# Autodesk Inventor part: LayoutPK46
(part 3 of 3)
    geometry: L1 (36.508, 713.207)-(-16.797, 670.2); L2 (-16.797, 670.2)-(-101.739, 335.484); L3 (-101.739, 335.484)-(-109.966, 2.719); L4 (8.288, -109.687)-(308.835, -86.978); L5 (308.835, -86.978)-(319.542, -83.051); L6 (19.324, 520.756)-(99.155, 741.781); L7 (99.155, 741.781)-(80.344, 748.575); L8 (80.344, 748.575)-(36.508, 713.207); L9 (1233.625, 258.517)-(1200.234, 261.682); L10 (1200.234, 261.682)-(1143.868, 239.874); L11 (1143.868, 239.874)-(1177.667, 236.867); L12 (1177.667, 236.867)-(1233.625, 258.517); L13 (967.076, 171.475)-(1143.868, 239.874); L14 (1181.276, 227.541)-(976.097, 148.159); L15 (976.097, 148.159)-(967.076, 171.475); L16 (1237.234, 249.191)-(1233.625, 258.517); L17 (1177.667, 236.867)-(1181.276, 227.541); L18 (1181.276, 227.541)-(1237.234, 249.191); L19 (332.219, -99.88)-(327.869, -88.635); L20 (332.219, -99.88)-(340.093, -96.834); L21 (327.869, -88.635)-(326.446, -84.958); L22 (630.662, 15.585)-(695.946, 40.843); L23 (340.093, -96.834)-(630.662, 15.585); L24 (971.406, 160.283)-(964.544, 144.762); L25 (971.406, 160.283)-(969.963, 164.014); L26 (695.946, 40.843)-(690.173, 55.765); L27 (969.963, 164.014)-(690.173, 55.765); L28 (695.946, 40.843)-(964.544, 144.762); L29 (271.723, 1081.905)-(246.908, 1104.472); L30 (246.908, 1104.472)-(15.69, 814.708); L31 (11.012, 759.335)-(43.462, 700.624); L32 (47.21, 660.849)-(-0.759, 514.651); L33 (556.412, -14.214)-(696.307, 39.911); L34 (696.307, 39.911)-(695.946, 40.843); L35 (594.585, 649.257)-(271.723, 1081.905); L36 (459.694, 596.673)-(459.353, 596.937); L37 (459.353, 596.937)-(498.23, 611.978); L38 (1112.062, 227.901)-(576.694, 642.28); L39 (995.062, 182.294)-(998.041, 183.455); L40 (499.228, 612.083)-(459.694, 596.673); L41 (459.694, 596.673)-(526.939, 544.624); L42 (606.946, 482.699)-(686.952, 420.773); L43 (766.958, 358.848)-(846.965, 296.922); L44 (926.971, 234.997)-(985.819, 189.448); L45 (995.055, 182.3)-(995.062, 182.294); L46 (998.041, 183.455)-(1130.882, 235.237); L47 (985.819, 189.448)-(995.055, 182.3); L48 (1130.882, 235.237)-(595.514, 649.616); C1 r 60 at (0, 0); C2 r 85 at (-189.66, 366.918); C3 r 25 at (54.772, 783.522); C4 r 62.5 at (-189.66, 366.918); A1 r 110 centre (0, 0) between (-109.966, 2.719) and (8.288, -109.687); A2 r 408 centre (403.06, 382.155) between (19.324, 520.756) and (16.94, 513.969); A3 r 50 centre (54.772, 783.522) between (15.69, 814.708) and (11.012, 759.335); A4 r 50 centre (-0.298, 676.437) between (47.21, 660.849) and (43.462, 700.624); A5 r 425 centre (403.06, 382.155) between (-0.759, 514.651) and (556.412, -14.214); 1 further point
    constraints: 96 end point, 10 point on circle, 9 centre point, 6 point on line
  sketch "A$C70327705_4"
    geometry: L1 (1293.342, 14.877)-(652.519, 14.877); L2 (1112.519, 47.877)-(1112.519, 51.877); L3 (652.519, 25)-(652.519, 14.997); L4 (652.519, 0)-(437.177, 0); L5 (437.177, 0)-(416.627, 29.348); L6 (662.519, 24.877)-(652.519, 24.877); L7 (1392.519, 34.877)-(1392.519, 44.877); L8 (1112.519, 34.877)-(1112.519, 59.877); L9 (1293.342, 34.877)-(1112.519, 34.877); L10 (1112.519, 59.877)-(1362.519, 59.877); L11 (1392.519, 44.877)-(1362.519, 59.877); L12 (936.663, 615.946)-(1277.997, 59.877); L13 (432.979, 926.11)-(441.861, 861.091); L14 (777.519, 1162.877)-(457.322, 976.064); L15 (116.871, 116.614)-(247.396, 77.132); L16 (100.413, 392.297)-(47.142, 264.117); L17 (374.881, 853.013)-(360.531, 832.814); L18 (440.113, 873.889)-(374.881, 853.013); L19 (9.07, 588.157)-(247.396, 77.132); L20 (662.519, 24.877)-(1293.342, 24.877); L21 (662.519, 34.877)-(1293.342, 34.877); L22 (679.974, 1088.415)-(349.973, 695.135); L23 (686.501, 1080.636)-(357.633, 688.707); L24 (1293.342, 14.877)-(1293.342, 24.877); L25 (1293.342, 24.877)-(1293.342, 34.877); L26 (936.663, 615.946)-(784.916, 1137.456); L27 (782.039, 1147.342)-(777.519, 1162.877); L28 (874.123, 1234.796)-(868.202, 1201.213); L29 (883.971, 1233.059)-(878.05, 1199.476); L30 (863.354, 1194.289)-(679.974, 1088.415); L31 (874.123, 1234.796)-(883.971, 1233.059); L32 (1293.342, 34.877)-(1392.519, 34.877); L33 (686.501, 1080.636)-(868.354, 1185.629); L34 (652.519, 0)-(652.519, 14.997); L35 (602.285, 29.348)-(293.569, 29.348); L36 (259.584, 50.998)-(247.396, 77.132); L37 (69.748, 731.714)-(508.737, 884.343); C1 r 25 at (482.519, 932.877); C2 r 45 at (104.231, 632.537); A1 r 50 centre (482.519, 932.877) between (457.322, 976.064) and (432.979, 926.11); A2 r 40 centre (148.72, 221.902) between (162.34, 259.512) and (186.286, 208.165); A3 r 110 centre (148.72, 221.902) between (47.142, 264.117) and (116.871, 116.614); A4 r 105 centre (104.231, 632.537) between (69.748, 731.714) and (9.07, 588.157); A5 r 408 centre (662.519, 432.877) between (349.973, 695.135) and (662.519, 24.877); A6 r 398 centre (662.519, 432.877) between (357.633, 688.707) and (662.519, 34.877); A7 r 37.5 centre (293.569, 66.848) between (259.584, 50.998) and (293.569, 29.348); A8 r 10 centre (858.354, 1202.949) between (863.354, 1194.289) and (868.202, 1201.213); A9 r 20 centre (858.354, 1202.949) between (868.354, 1185.629) and (878.05, 1199.476); 1 further point
    constraints: 74 end point, 20 point on circle, 16 point on line, 11 centre point
  sketch "A$C60B60B97_4"
    geometry: 1 further point
  sketch "Borders Default Border_9.00X_5"
    geometry: L1 (171.45, 114.3)-(171.45, 3771.9); L2 (171.45, 3771.9)-(4857.75, 3771.9); L3 (4857.75, 3771.9)-(4857.75, 114.3); L4 (4857.75, 114.3)-(171.45, 114.3); L5 (2514.6, 57.15)-(2514.6, 114.3); L6 (2514.6, 114.3)-(2494.803, 80.01); L7 (2494.803, 80.01)-(2534.397, 80.01); L8 (2534.397, 80.01)-(2514.6, 114.3); L9 (2514.6, 3829.05)-(2514.6, 3771.9); L10 (2514.6, 3771.9)-(2494.803, 3806.19); L11 (2494.803, 3806.19)-(2534.397, 3806.19); L12 (2534.397, 3806.19)-(2514.6, 3771.9); L13 (114.3, 1943.1)-(171.45, 1943.1); L14 (171.45, 1943.1)-(137.16, 1962.897); L15 (137.16, 1962.897)-(137.16, 1923.303); L16 (137.16, 1923.303)-(171.45, 1943.1); L17 (4914.9, 1943.1)-(4857.75, 1943.1); L18 (4857.75, 1943.1)-(4892.04, 1962.897); L19 (4892.04, 1962.897)-(4892.04, 1923.303); L20 (4892.04, 1923.303)-(4857.75, 1943.1); L21 (1257.3, 114.3)-(1257.3, 77.724); L22 (1257.3, 3771.9)-(1257.3, 3808.476); L23 (3771.9, 114.3)-(3771.9, 77.724); L24 (3771.9, 3771.9)-(3771.9, 3808.476); L25 (171.45, 971.55)-(134.874, 971.55); L26 (4857.75, 971.55)-(4894.326, 971.55); L27 (171.45, 2914.65)-(134.874, 2914.65); L28 (4857.75, 2914.65)-(4894.326, 2914.65); 17 further points
    constraints: 56 end point, 8 point on line, 4 midpoint, 16 other
  sketch "_Closed_6"
    geometry: L1 (-25.4, 4.233)-(0, 0); L2 (0, 0)-(-25.4, -4.233); L3 (-25.4, 4.233)-(-25.4, -4.233); L4 (0, 0)-(-25.4, 0); 1 further point
    constraints: 8 end point, 1 midpoint
  sketch "DatumFilled45_6"
    geometry: L1 (0, 25.4)-(0, -25.4); L2 (0, -25.4)-(-25.4, 0); L3 (-25.4, 0)-(0, 25.4); L4 (0, 25.4)-(0, -25.4); L5 (0, -25.4)-(0, 25.4); L6 (0, 25.4)-(-25.4, 0); L7 (-25.4, 0)-(0, 25.4); 1 further point
    constraints: 14 end point
  sketch "Filled-1_6"
    geometry: L1 (-25.4, 0)-(0, 0); L2 (-25.4, -2.527)-(0, 0); L3 (0, 0)-(-25.4, 2.527); L4 (-25.4, 2.527)-(-25.4, -2.527); L5 (-25.4, -2.527)-(0, 0); L6 (0, 0)-(-25.4, -2.527); L7 (-25.4, -2.527)-(-25.4, 2.527); L8 (-25.4, 2.527)-(-25.4, -2.527); L9 (-25.4, -2.527)-(0, 0); L10 (0, 0)-(-25.4, 2.527); L11 (-25.4, 2.527)-(-25.4, -2.527); 1 further point
    constraints: 22 end point, 4 midpoint
  sketch "Borders Default Border_6"
    geometry: L1 (19.05, 12.7)-(19.05, 419.1); L2 (19.05, 419.1)-(539.75, 419.1); L3 (539.75, 419.1)-(539.75, 12.7); L4 (539.75, 12.7)-(19.05, 12.7); L5 (279.4, 6.35)-(279.4, 12.7); L6 (279.4, 12.7)-(277.2, 8.89); L7 (277.2, 8.89)-(281.6, 8.89); L8 (281.6, 8.89)-(279.4, 12.7); L9 (279.4, 425.45)-(279.4, 419.1); L10 (279.4, 419.1)-(277.2, 422.91); L11 (277.2, 422.91)-(281.6, 422.91); L12 (281.6, 422.91)-(279.4, 419.1); L13 (12.7, 215.9)-(19.05, 215.9); L14 (19.05, 215.9)-(15.24, 218.1); L15 (15.24, 218.1)-(15.24, 213.7); L16 (15.24, 213.7)-(19.05, 215.9); L17 (546.1, 215.9)-(539.75, 215.9); L18 (539.75, 215.9)-(543.56, 218.1); L19 (543.56, 218.1)-(543.56, 213.7); L20 (543.56, 213.7)-(539.75, 215.9); L21 (139.7, 12.7)-(139.7, 8.636); L22 (139.7, 419.1)-(139.7, 423.164); L23 (419.1, 12.7)-(419.1, 8.636); L24 (419.1, 419.1)-(419.1, 423.164); L25 (19.05, 107.95)-(14.986, 107.95); L26 (539.75, 107.95)-(543.814, 107.95); L27 (19.05, 323.85)-(14.986, 323.85); L28 (539.75, 323.85)-(543.814, 323.85); 17 further points
    constraints: 56 end point, 8 point on line, 4 midpoint, 16 other
  sketch "GENAXEH_6"
    geometry: L1 (-25.4, 0)-(25.4, 0); 1 further point
    constraints: 2 end point
  sketch "Weldment_6"
    geometry: L1 (-362.49, 605.558)-(-187.308, 59.988); L2 (-48.402, -559.479)-(-89.17, -792.346); L3 (104.596, -840)-(155.018, -682.036); L4 (176.996, -25.915)-(5.037, 246.17); L5 (5.037, 246.17)-(-175.085, 674.867); L6 (-187.308, 59.988)-(-152.339, -48.916); L7 (-104.241, -121.383)-(-75.352, -146.192); L8 (-8.649, -332.41)-(-48.402, -559.479); L9 (155.018, -682.036)-(230.654, -445.083); L10 (-57.997, -88.254)-(-54.949, -85.206); L11 (-57.997, -85.206)-(-54.949, -88.254); C1 r 75 at (0, 0); C2 r 87 at (0, 0); C3 r 45 at (-267.278, 636.131); C4 r 45 at (9.332, -809.591); C5 r 1.524 at (-56.473, -86.73); A1 r 100 centre (-267.278, 636.131) between (-175.085, 674.867) and (-362.49, 605.558); A2 r 100 centre (9.332, -809.591) between (-89.17, -792.346) and (104.596, -840); A3 r 500 centre (-245.668, -293.04) between (250.28, -356.567) and (176.996, -25.915); A4 r 160 centre (0, 0) between (-152.339, -48.916) and (-104.241, -121.383); A5 r 200 centre (-205.653, -297.921) between (-8.649, -332.41) and (-75.352, -146.192); A6 r 500 centre (-245.668, -293.04) between (230.654, -445.083) and (250.28, -356.567); 1 further point
    constraints: 22 end point, 12 point on circle, 11 centre point
  sketch "Connector_6"
    geometry: L1 (157.164, 27.531)-(232.989, 74.957); L2 (483.604, 231.708)-(512.662, 249.882); L3 (76.449, -64.463)-(145.454, 17.372); L4 (449.028, 351.621)-(398.755, 320.177); L5 (509.104, 419.139)-(460.738, 361.78); L6 (526.921, 255.966)-(571.21, 267.162); L7 (232.989, 74.957)-(483.604, 231.708); L8 (398.755, 320.177)-(93.53, 129.27); L9 (529.743, 443.615)-(509.104, 419.139); L10 (79.271, 123.186)-(-24.509, 96.95); L11 (571.21, 267.162)-(630.701, 282.202); L12 (302.321, 205.82)-(305.369, 208.868); L13 (302.321, 208.868)-(305.369, 205.82); C1 r 45 at (0, 0); C2 r 45 at (606.192, 379.152); C3 r 1.524 at (303.845, 207.344); A1 r 50 centre (539.176, 207.491) between (526.921, 255.966) and (512.662, 249.882); A2 r 50 centre (183.678, -14.86) between (157.164, 27.531) and (145.454, 17.372); A3 r 50 centre (422.514, 394.012) between (449.028, 351.621) and (460.738, 361.78); A4 r 50 centre (67.016, 171.661) between (79.271, 123.186) and (93.53, 129.27); A5 r 100 centre (606.192, 379.152) between (630.701, 282.202) and (529.743, 443.615); A6 r 100 centre (0, 0) between (-24.509, 96.95) and (76.449, -64.463); 1 further point
    constraints: 26 end point, 12 point on circle, 9 centre point
  sketch "Base_6"
    geometry: L1 (278.529, -481.687)-(299.453, -447.453); L2 (295.917, -416.857)-(172.052, -291.319); L3 (95.022, -681.286)-(272.857, -489.184); L4 (108.329, 19.101)-(158.403, -264.884); L5 (-225.117, -660.979)-(-108.413, 18.617); L6 (-225.235, -722.613)-(-225.117, -660.979); L7 (-198.661, -766.881)-(-24.713, -859.13); L8 (3.19, -856.093)-(33.762, -830.109); L9 (48.097, -808.832)-(84.242, -699.551); L10 (0, 254)-(0, -254); L11 (-254, 0)-(254, 0); L12 (0, -346)-(0, -854); L13 (-254, -600)-(254, -600); L14 (37.419, -377.546)-(40.467, -374.498); L15 (37.419, -374.498)-(40.467, -377.546); C1 r 40 at (0, -600); C2 r 40 at (0, 0); C3 r 1.524 at (38.943, -376.022); A1 r 47.5 centre (238, -456.916) between (272.857, -489.184) and (278.529, -481.687); A2 r 25 centre (278.122, -434.416) between (299.453, -447.453) and (295.917, -416.857); A3 r 50 centre (207.644, -256.202) between (158.403, -264.884) and (172.052, -291.319); A4 r 50 centre (-175.235, -722.709) between (-225.235, -722.613) and (-198.661, -766.881); A5 r 50 centre (131.713, -715.252) between (95.022, -681.286) and (84.242, -699.551); A6 r 110 centre (0, 0) between (108.329, 19.101) and (-108.413, 18.617); A7 r 25 centre (-13, -837.043) between (-24.713, -859.13) and (3.19, -856.093); A8 r 47.5 centre (3, -793.916) between (33.762, -830.109) and (48.097, -808.832); 1 further point
    constraints: 30 end point, 16 point on circle, 11 centre point
  sketch "CenterSpan_6"
    geometry: L1 (273.969, -185.044)-(234.974, -284.945); L2 (36.362, 93.155)-(259.933, 5.887); L3 (12.317, -103.462)-(-16.542, -98.622); L4 (180.828, -183.299)-(-38.18, -97.813); L5 (437.598, -26.221)-(296.603, -162.71); L6 (-23.266, 102.39)-(214.339, 156.38); L7 (495.815, 30.136)-(437.598, -26.221); L8 (214.339, 156.38)-(404.104, 199.5); L9 (110.262, -93.996)-(113.31, -90.948); L10 (110.262, -90.948)-(113.31, -93.996); C1 r 82 at (0, 0); C2 r 82 at (223.572, -87.268); C3 r 50 at (426.262, 101.986); C4 r 58.472 at (158.121, -254.947); C5 r 1.524 at (111.786, -92.472); A1 r 90 centre (-2.571, -192.223) between (81.268, -224.948) and (12.317, -103.462); A2 r 60 centre (329.862, -206.861) between (290.003, -162.013) and (273.969, -185.044); A3 r 100 centre (223.572, -87.267) between (290.003, -162.013) and (259.933, 5.887); A4 r 100 centre (0, 0) between (36.362, 93.155) and (-16.542, -98.622); A5 r 105 centre (223.572, -87.268) between (189.942, -186.736) and (296.603, -162.71); A6 r 105 centre (0, 0) between (-23.266, 102.39) and (-38.18, -97.813); A7 r 100 centre (426.262, 101.986) between (495.815, 30.136) and (404.104, 199.5); A8 r 82.5 centre (158.121, -254.946) between (81.268, -224.948) and (234.974, -284.944); 1 further point
    constraints: 20 end point, 17 point on circle, 13 centre point, 1 point on line
  sketch "Arm_6"
    geometry: L1 (-25.496, -107.005)-(137.409, -145.82); L2 (2597.068, -901.099)-(2521.421, -896.025); L3 (2257.231, -771.408)-(2076.35, -579.673); L4 (2076.35, -579.673)-(2063.205, -583.463); L5 (2043.846, -578.704)-(1704.981, -254.849); L6 (1379.251, -95.221)-(16.283, 108.788); L7 (137.409, -145.82)-(1374.243, -440.518); L8 (1601.431, -691.827)-(2199.578, -1052.198); L9 (2469.644, -1123.775)-(2592.355, -1120.82); L10 (1293.329, -509.09)-(1296.377, -506.042); L11 (1293.329, -506.042)-(1296.377, -509.09); C1 r 40.528 at (0, 0); C2 r 40.528 at (2589.706, -1010.852); C3 r 1.524 at (1294.853, -507.566); A1 r 400 centre (2548.19, -496.921) between (2482.623, -891.511) and (2521.421, -896.025); A2 r 110 centre (2589.706, -1010.852) between (2597.994, -1120.539) and (2597.068, -901.099); A3 r 400 centre (2548.19, -496.921) between (2257.231, -771.408) and (2482.623, -891.511); A4 r 20 centre (2057.664, -564.246) between (2043.846, -578.704) and (2063.205, -583.463); A5 r 600 centre (1290.432, -688.61) between (1704.981, -254.849) and (1379.251, -95.221); A6 r 70 centre (1358.018, -508.612) between (1423.227, -534.065) and (1374.243, -440.518); A7 r 100 centre (1516.382, -570.427) between (1423.227, -534.065) and (1519.438, -670.38); A8 r 150 centre (1524.023, -820.31) between (1601.431, -691.827) and (1519.438, -670.38); A9 r 500 centre (2457.606, -623.92) between (2199.578, -1052.198) and (2469.644, -1123.775); A10 r 110 centre (0, 0) between (16.283, 108.788) and (-25.496, -107.005); 1 further point
    constraints: 22 end point, 20 point on circle, 13 centre point
  sketch "Bucket_6"
    geometry: L1 (0, -20)-(-640.824, -20); L2 (99.176, 0)-(99.176, 10); L3 (-180.824, 0)-(-180.824, 25); L4 (0, 0)-(-180.824, 0); L5 (-180.824, 25)-(69.176, 25); L6 (99.176, 10)-(69.176, 25); L7 (-356.679, 581.068)-(-15.346, 25); L8 (-860.363, 891.232)-(-851.481, 826.214); L9 (-515.824, 1128)-(-836.02, 941.187); L10 (-1280.042, 545.155)-(-976.734, 19.869); L11 (-630.824, -10)-(0, -10); L12 (-630.824, 0)-(0, 0); L13 (-613.369, 1053.537)-(-943.37, 660.257); L14 (-606.842, 1045.759)-(-935.709, 653.829); L15 (0, -20)-(0, -10); L16 (0, -10)-(0, 0); L17 (-356.679, 581.068)-(-508.427, 1102.579); L18 (-511.303, 1112.465)-(-515.824, 1128); L19 (-419.219, 1199.918)-(-425.141, 1166.336); L20 (-409.371, 1198.182)-(-415.292, 1164.599); L21 (-429.989, 1159.412)-(-613.369, 1053.537); L22 (-419.219, 1199.918)-(-409.371, 1198.182); L23 (0, 0)-(99.176, 0); L24 (-606.842, 1045.759)-(-424.989, 1150.752); L25 (-691.058, -5.529)-(-949.951, -5.529); L26 (-1223.594, 696.836)-(-784.605, 849.466); L27 (-1185.527, 84.913)-(-968.841, -1.886); L28 (-1246.2, 229.24)-(-1184.02, 378.858); L29 (-1183.986, 378.801)-(-1121.865, 527.323); L30 (-784.605, 849.466)-(-1109.735, 544.789); C1 r 25 at (-810.824, 898); C2 r 45 at (-1189.112, 597.66); C3 r 40 at (-1144.623, 187.025); A1 r 50 centre (-810.824, 898) between (-836.02, 941.187) and (-860.363, 891.232); A2 r 110 centre (-1144.623, 187.025) between (-1246.2, 229.24) and (-1176.471, 81.737); A3 r 105 centre (-1189.112, 597.66) between (-1223.594, 696.836) and (-1280.042, 545.155); A4 r 408 centre (-630.824, 398) between (-943.37, 660.257) and (-630.824, -10); A5 r 418 centre (-630.824, 398) between (-739.856, -5.529) and (-630.824, -20); A6 r 398 centre (-630.824, 398) between (-935.709, 653.829) and (-630.824, 0); A7 r 10 centre (-434.989, 1168.072) between (-429.989, 1159.412) and (-425.141, 1166.336); A8 r 20 centre (-434.989, 1168.072) between (-424.989, 1150.752) and (-415.292, 1164.599); A9 r 50.8 centre (-949.951, 45.271) between (-968.841, -1.886) and (-949.951, -5.529); A10 r 50.8 centre (-1074.999, 507.721) between (-1109.735, 544.789) and (-1121.865, 527.323); A11 r 50.8 centre (-932.741, 45.271) between (-976.734, 19.869) and (-932.741, -5.529); 1 further point
    constraints: 60 end point, 24 point on circle, 14 centre point, 11 point on line
  sketch "FrontBucket_6"
    geometry: L1 (36.508, 713.207)-(-16.797, 670.2); L2 (-16.797, 670.2)-(-101.739, 335.484); L3 (-101.739, 335.484)-(-109.966, 2.719); L4 (8.288, -109.687)-(308.835, -86.978); L5 (308.835, -86.978)-(319.542, -83.051); L6 (19.324, 520.756)-(99.155, 741.781); L7 (99.155, 741.781)-(80.344, 748.575); L8 (80.344, 748.575)-(36.508, 713.207); L9 (1233.625, 258.517)-(1200.234, 261.682); L10 (1200.234, 261.682)-(1143.868, 239.874); L11 (1143.868, 239.874)-(1177.667, 236.867); L12 (1177.667, 236.867)-(1233.625, 258.517); L13 (967.076, 171.475)-(1143.868, 239.874); L14 (1181.276, 227.541)-(976.097, 148.159); L15 (976.097, 148.159)-(967.076, 171.475); L16 (1237.234, 249.191)-(1233.625, 258.517); L17 (1177.667, 236.867)-(1181.276, 227.541); L18 (1181.276, 227.541)-(1237.234, 249.191); L19 (332.219, -99.88)-(327.869, -88.635); L20 (332.219, -99.88)-(340.093, -96.834); L21 (327.869, -88.635)-(326.446, -84.958); L22 (630.662, 15.585)-(695.946, 40.843); L23 (340.093, -96.834)-(630.662, 15.585); L24 (971.406, 160.283)-(964.544, 144.762); L25 (971.406, 160.283)-(969.963, 164.014); L26 (695.946, 40.843)-(690.173, 55.765); L27 (969.963, 164.014)-(690.173, 55.765); L28 (695.946, 40.843)-(964.544, 144.762); L29 (271.723, 1081.905)-(246.908, 1104.472); L30 (246.908, 1104.472)-(15.69, 814.708); L31 (11.012, 759.335)-(43.462, 700.624); L32 (47.21, 660.849)-(-0.759, 514.651); L33 (556.412, -14.214)-(696.307, 39.911); L34 (696.307, 39.911)-(695.946, 40.843); L35 (594.585, 649.257)-(271.723, 1081.905); L36 (459.694, 596.673)-(459.353, 596.937); L37 (459.353, 596.937)-(498.23, 611.978); L38 (1112.062, 227.901)-(576.694, 642.28); L39 (995.062, 182.294)-(998.041, 183.455); L40 (499.228, 612.083)-(459.694, 596.673); L41 (459.694, 596.673)-(526.939, 544.624); L42 (606.946, 482.699)-(686.952, 420.773); L43 (766.958, 358.848)-(846.965, 296.922); L44 (926.971, 234.997)-(985.819, 189.448); L45 (995.055, 182.3)-(995.062, 182.294); L46 (998.041, 183.455)-(1130.882, 235.237); L47 (985.819, 189.448)-(995.055, 182.3); L48 (1130.882, 235.237)-(595.514, 649.616); C1 r 60 at (0, 0); C2 r 85 at (-189.66, 366.918); C3 r 25 at (54.772, 783.522); C4 r 62.5 at (-189.66, 366.918); A1 r 110 centre (0, 0) between (-109.966, 2.719) and (8.288, -109.687); A2 r 408 centre (403.06, 382.155) between (19.324, 520.756) and (16.94, 513.969); A3 r 50 centre (54.772, 783.522) between (15.69, 814.708) and (11.012, 759.335); A4 r 50 centre (-0.298, 676.437) between (47.21, 660.849) and (43.462, 700.624); A5 r 425 centre (403.06, 382.155) between (-0.759, 514.651) and (556.412, -14.214); 1 further point
    constraints: 96 end point, 10 point on circle, 9 centre point, 6 point on line
  sketch "A$C70327705_5"
    geometry: L1 (1293.342, 14.877)-(652.519, 14.877); L2 (1112.519, 47.877)-(1112.519, 51.877); L3 (652.519, 25)-(652.519, 14.997); L4 (652.519, 0)-(437.177, 0); L5 (437.177, 0)-(416.627, 29.348); L6 (662.519, 24.877)-(652.519, 24.877); L7 (1392.519, 34.877)-(1392.519, 44.877); L8 (1112.519, 34.877)-(1112.519, 59.877); L9 (1293.342, 34.877)-(1112.519, 34.877); L10 (1112.519, 59.877)-(1362.519, 59.877); L11 (1392.519, 44.877)-(1362.519, 59.877); L12 (936.663, 615.946)-(1277.997, 59.877); L13 (432.979, 926.11)-(441.861, 861.091); L14 (777.519, 1162.877)-(457.322, 976.064); L15 (116.871, 116.614)-(247.396, 77.132); L16 (100.413, 392.297)-(47.142, 264.117); L17 (374.881, 853.013)-(360.531, 832.814); L18 (440.113, 873.889)-(374.881, 853.013); L19 (9.07, 588.157)-(247.396, 77.132); L20 (662.519, 24.877)-(1293.342, 24.877); L21 (662.519, 34.877)-(1293.342, 34.877); L22 (679.974, 1088.415)-(349.973, 695.135); L23 (686.501, 1080.636)-(357.633, 688.707); L24 (1293.342, 14.877)-(1293.342, 24.877); L25 (1293.342, 24.877)-(1293.342, 34.877); L26 (936.663, 615.946)-(784.916, 1137.456); L27 (782.039, 1147.342)-(777.519, 1162.877); L28 (874.123, 1234.796)-(868.202, 1201.213); L29 (883.971, 1233.059)-(878.05, 1199.476); L30 (863.354, 1194.289)-(679.974, 1088.415); L31 (874.123, 1234.796)-(883.971, 1233.059); L32 (1293.342, 34.877)-(1392.519, 34.877); L33 (686.501, 1080.636)-(868.354, 1185.629); L34 (652.519, 0)-(652.519, 14.997); L35 (602.285, 29.348)-(293.569, 29.348); L36 (259.584, 50.998)-(247.396, 77.132); L37 (69.748, 731.714)-(508.737, 884.343); C1 r 25 at (482.519, 932.877); C2 r 45 at (104.231, 632.537); A1 r 50 centre (482.519, 932.877) between (457.322, 976.064) and (432.979, 926.11); A2 r 40 centre (148.72, 221.902) between (162.34, 259.512) and (186.286, 208.165); A3 r 110 centre (148.72, 221.902) between (47.142, 264.117) and (116.871, 116.614); A4 r 105 centre (104.231, 632.537) between (69.748, 731.714) and (9.07, 588.157); A5 r 408 centre (662.519, 432.877) between (349.973, 695.135) and (662.519, 24.877); A6 r 398 centre (662.519, 432.877) between (357.633, 688.707) and (662.519, 34.877); A7 r 37.5 centre (293.569, 66.848) between (259.584, 50.998) and (293.569, 29.348); A8 r 10 centre (858.354, 1202.949) between (863.354, 1194.289) and (868.202, 1201.213); A9 r 20 centre (858.354, 1202.949) between (868.354, 1185.629) and (878.05, 1199.476); 1 further point
    constraints: 74 end point, 20 point on circle, 16 point on line, 11 centre point
  sketch "A$C60B60B97_5"
    geometry: 1 further point
  sketch "Borders Default Border_9.00X_6"
    geometry: L1 (171.45, 114.3)-(171.45, 3771.9); L2 (171.45, 3771.9)-(4857.75, 3771.9); L3 (4857.75, 3771.9)-(4857.75, 114.3); L4 (4857.75, 114.3)-(171.45, 114.3); L5 (2514.6, 57.15)-(2514.6, 114.3); L6 (2514.6, 114.3)-(2494.803, 80.01); L7 (2494.803, 80.01)-(2534.397, 80.01); L8 (2534.397, 80.01)-(2514.6, 114.3); L9 (2514.6, 3829.05)-(2514.6, 3771.9); L10 (2514.6, 3771.9)-(2494.803, 3806.19); L11 (2494.803, 3806.19)-(2534.397, 3806.19); L12 (2534.397, 3806.19)-(2514.6, 3771.9); L13 (114.3, 1943.1)-(171.45, 1943.1); L14 (171.45, 1943.1)-(137.16, 1962.897); L15 (137.16, 1962.897)-(137.16, 1923.303); L16 (137.16, 1923.303)-(171.45, 1943.1); L17 (4914.9, 1943.1)-(4857.75, 1943.1); L18 (4857.75, 1943.1)-(4892.04, 1962.897); L19 (4892.04, 1962.897)-(4892.04, 1923.303); L20 (4892.04, 1923.303)-(4857.75, 1943.1); L21 (1257.3, 114.3)-(1257.3, 77.724); L22 (1257.3, 3771.9)-(1257.3, 3808.476); L23 (3771.9, 114.3)-(3771.9, 77.724); L24 (3771.9, 3771.9)-(3771.9, 3808.476); L25 (171.45, 971.55)-(134.874, 971.55); L26 (4857.75, 971.55)-(4894.326, 971.55); L27 (171.45, 2914.65)-(134.874, 2914.65); L28 (4857.75, 2914.65)-(4894.326, 2914.65); 17 further points
    constraints: 56 end point, 8 point on line, 4 midpoint, 16 other
  sketch "_Closed_7"
    geometry: L1 (-25.4, 4.233)-(0, 0); L2 (0, 0)-(-25.4, -4.233); L3 (-25.4, 4.233)-(-25.4, -4.233); L4 (0, 0)-(-25.4, 0); 1 further point
    constraints: 8 end point, 1 midpoint
  sketch "DatumFilled45_7"
    geometry: L1 (0, 25.4)-(0, -25.4); L2 (0, -25.4)-(-25.4, 0); L3 (-25.4, 0)-(0, 25.4); L4 (0, 25.4)-(0, -25.4); L5 (0, -25.4)-(0, 25.4); L6 (0, 25.4)-(-25.4, 0); L7 (-25.4, 0)-(0, 25.4); 1 further point
    constraints: 14 end point
  sketch "Filled-1_7"
    geometry: L1 (-25.4, 0)-(0, 0); L2 (-25.4, -2.527)-(0, 0); L3 (0, 0)-(-25.4, 2.527); L4 (-25.4, 2.527)-(-25.4, -2.527); L5 (-25.4, -2.527)-(0, 0); L6 (0, 0)-(-25.4, -2.527); L7 (-25.4, -2.527)-(-25.4, 2.527); L8 (-25.4, 2.527)-(-25.4, -2.527); L9 (-25.4, -2.527)-(0, 0); L10 (0, 0)-(-25.4, 2.527); L11 (-25.4, 2.527)-(-25.4, -2.527); 1 further point
    constraints: 22 end point, 4 midpoint
  sketch "Borders Default Border_7"
    geometry: L1 (19.05, 12.7)-(19.05, 419.1); L2 (19.05, 419.1)-(539.75, 419.1); L3 (539.75, 419.1)-(539.75, 12.7); L4 (539.75, 12.7)-(19.05, 12.7); L5 (279.4, 6.35)-(279.4, 12.7); L6 (279.4, 12.7)-(277.2, 8.89); L7 (277.2, 8.89)-(281.6, 8.89); L8 (281.6, 8.89)-(279.4, 12.7); L9 (279.4, 425.45)-(279.4, 419.1); L10 (279.4, 419.1)-(277.2, 422.91); L11 (277.2, 422.91)-(281.6, 422.91); L12 (281.6, 422.91)-(279.4, 419.1); L13 (12.7, 215.9)-(19.05, 215.9); L14 (19.05, 215.9)-(15.24, 218.1); L15 (15.24, 218.1)-(15.24, 213.7); L16 (15.24, 213.7)-(19.05, 215.9); L17 (546.1, 215.9)-(539.75, 215.9); L18 (539.75, 215.9)-(543.56, 218.1); L19 (543.56, 218.1)-(543.56, 213.7); L20 (543.56, 213.7)-(539.75, 215.9); L21 (139.7, 12.7)-(139.7, 8.636); L22 (139.7, 419.1)-(139.7, 423.164); L23 (419.1, 12.7)-(419.1, 8.636); L24 (419.1, 419.1)-(419.1, 423.164); L25 (19.05, 107.95)-(14.986, 107.95); L26 (539.75, 107.95)-(543.814, 107.95); L27 (19.05, 323.85)-(14.986, 323.85); L28 (539.75, 323.85)-(543.814, 323.85); 17 further points
    constraints: 56 end point, 8 point on line, 4 midpoint, 16 other
  sketch "GENAXEH_7"
    geometry: L1 (-25.4, 0)-(25.4, 0); 1 further point
    constraints: 2 end point
  sketch "Weldment_7"
    geometry: L1 (-362.49, 605.558)-(-187.308, 59.988); L2 (-48.402, -559.479)-(-89.17, -792.346); L3 (104.596, -840)-(155.018, -682.036); L4 (176.996, -25.915)-(5.037, 246.17); L5 (5.037, 246.17)-(-175.085, 674.867); L6 (-187.308, 59.988)-(-152.339, -48.916); L7 (-104.241, -121.383)-(-75.352, -146.192); L8 (-8.649, -332.41)-(-48.402, -559.479); L9 (155.018, -682.036)-(230.654, -445.083); L10 (-57.997, -88.254)-(-54.949, -85.206); L11 (-57.997, -85.206)-(-54.949, -88.254); C1 r 75 at (0, 0); C2 r 87 at (0, 0); C3 r 45 at (-267.278, 636.131); C4 r 45 at (9.332, -809.591); C5 r 1.524 at (-56.473, -86.73); A1 r 100 centre (-267.278, 636.131) between (-175.085, 674.867) and (-362.49, 605.558); A2 r 100 centre (9.332, -809.591) between (-89.17, -792.346) and (104.596, -840); A3 r 500 centre (-245.668, -293.04) between (250.28, -356.567) and (176.996, -25.915); A4 r 160 centre (0, 0) between (-152.339, -48.916) and (-104.241, -121.383); A5 r 200 centre (-205.653, -297.921) between (-8.649, -332.41) and (-75.352, -146.192); A6 r 500 centre (-245.668, -293.04) between (230.654, -445.083) and (250.28, -356.567); 1 further point
    constraints: 22 end point, 12 point on circle, 11 centre point
  sketch "Connector_7"
    geometry: L1 (157.164, 27.531)-(232.989, 74.957); L2 (483.604, 231.708)-(512.662, 249.882); L3 (76.449, -64.463)-(145.454, 17.372); L4 (449.028, 351.621)-(398.755, 320.177); L5 (509.104, 419.139)-(460.738, 361.78); L6 (526.921, 255.966)-(571.21, 267.162); L7 (232.989, 74.957)-(483.604, 231.708); L8 (398.755, 320.177)-(93.53, 129.27); L9 (529.743, 443.615)-(509.104, 419.139); L10 (79.271, 123.186)-(-24.509, 96.95); L11 (571.21, 267.162)-(630.701, 282.202); L12 (302.321, 205.82)-(305.369, 208.868); L13 (302.321, 208.868)-(305.369, 205.82); C1 r 45 at (0, 0); C2 r 45 at (606.192, 379.152); C3 r 1.524 at (303.845, 207.344); A1 r 50 centre (539.176, 207.491) between (526.921, 255.966) and (512.662, 249.882); A2 r 50 centre (183.678, -14.86) between (157.164, 27.531) and (145.454, 17.372); A3 r 50 centre (422.514, 394.012) between (449.028, 351.621) and (460.738, 361.78); A4 r 50 centre (67.016, 171.661) between (79.271, 123.186) and (93.53, 129.27); A5 r 100 centre (606.192, 379.152) between (630.701, 282.202) and (529.743, 443.615); A6 r 100 centre (0, 0) between (-24.509, 96.95) and (76.449, -64.463); 1 further point
    constraints: 26 end point, 12 point on circle, 9 centre point
  sketch "Base_7"
    geometry: L1 (278.529, -481.687)-(299.453, -447.453); L2 (295.917, -416.857)-(172.052, -291.319); L3 (95.022, -681.286)-(272.857, -489.184); L4 (108.329, 19.101)-(158.403, -264.884); L5 (-249.445, -802.646)-(-108.413, 18.617); L6 (3.19, -856.093)-(33.762, -830.109); L7 (48.097, -808.832)-(84.242, -699.551); L8 (-13, -862.043)-(-199.378, -862.043); L9 (37.419, -377.546)-(40.467, -374.498); L10 (37.419, -374.498)-(40.467, -377.546); C1 r 40 at (0, -600); C2 r 40 at (0, 0); C3 r 1.524 at (38.943, -376.022); A1 r 47.5 centre (238, -456.916) between (272.857, -489.184) and (278.529, -481.687); A2 r 25 centre (278.122, -434.416) between (299.453, -447.453) and (295.917, -416.857); A3 r 50 centre (207.644, -256.202) between (158.403, -264.884) and (172.052, -291.319); A4 r 50 centre (131.713, -715.252) between (95.022, -681.286) and (84.242, -699.551); A5 r 110 centre (0, 0) between (108.329, 19.101) and (-108.413, 18.617); A6 r 25 centre (-13, -837.043) between (-15.705, -861.897) and (3.19, -856.093); A7 r 47.5 centre (3, -793.916) between (33.762, -830.109) and (48.097, -808.832); A8 r 50.8 centre (-199.378, -811.243) between (-249.445, -802.646) and (-199.378, -862.043); 1 further point
    constraints: 20 end point, 17 point on circle, 11 centre point
  sketch "CenterSpan_7"
    geometry: L1 (273.969, -185.044)-(234.974, -284.945); L2 (36.362, 93.155)-(259.933, 5.887); L3 (12.317, -103.462)-(-16.542, -98.622); L4 (180.828, -183.299)-(-38.18, -97.813); L5 (437.598, -26.221)-(296.603, -162.71); L6 (-23.266, 102.39)-(214.339, 156.38); L7 (495.815, 30.136)-(437.598, -26.221); L8 (214.339, 156.38)-(404.104, 199.5); L9 (110.262, -93.996)-(113.31, -90.948); L10 (110.262, -90.948)-(113.31, -93.996); C1 r 82 at (0, 0); C2 r 82 at (223.572, -87.268); C3 r 50 at (426.262, 101.986); C4 r 58.472 at (158.121, -254.947); C5 r 1.524 at (111.786, -92.472); A1 r 90 centre (-2.571, -192.223) between (81.268, -224.948) and (12.317, -103.462); A2 r 60 centre (329.862, -206.861) between (290.003, -162.013) and (273.969, -185.044); A3 r 100 centre (223.572, -87.267) between (290.003, -162.013) and (259.933, 5.887); A4 r 100 centre (0, 0) between (36.362, 93.155) and (-16.542, -98.622); A5 r 105 centre (223.572, -87.268) between (189.942, -186.736) and (296.603, -162.71); A6 r 105 centre (0, 0) between (-23.266, 102.39) and (-38.18, -97.813); A7 r 100 centre (426.262, 101.986) between (495.815, 30.136) and (404.104, 199.5); A8 r 82.5 centre (158.121, -254.946) between (81.268, -224.948) and (234.974, -284.944); 1 further point
    constraints: 20 end point, 17 point on circle, 13 centre point, 1 point on line
  sketch "Arm_7"
    geometry: L1 (-25.496, -107.005)-(137.409, -145.82); L2 (2597.068, -901.099)-(2521.421, -896.025); L3 (2257.231, -771.408)-(2076.35, -579.673); L4 (2076.35, -579.673)-(2063.205, -583.463); L5 (2043.846, -578.704)-(1704.981, -254.849); L6 (1379.251, -95.221)-(16.283, 108.788); L7 (137.409, -145.82)-(1374.243, -440.518); L8 (1601.431, -691.827)-(2199.578, -1052.198); L9 (2469.644, -1123.775)-(2592.355, -1120.82); L10 (1293.329, -509.09)-(1296.377, -506.042); L11 (1293.329, -506.042)-(1296.377, -509.09); C1 r 40.528 at (0, 0); C2 r 40.528 at (2589.706, -1010.852); C3 r 1.524 at (1294.853, -507.566); A1 r 400 centre (2548.19, -496.921) between (2482.623, -891.511) and (2521.421, -896.025); A2 r 110 centre (2589.706, -1010.852) between (2597.994, -1120.539) and (2597.068, -901.099); A3 r 400 centre (2548.19, -496.921) between (2257.231, -771.408) and (2482.623, -891.511); A4 r 20 centre (2057.664, -564.246) between (2043.846, -578.704) and (2063.205, -583.463); A5 r 600 centre (1290.432, -688.61) between (1704.981, -254.849) and (1379.251, -95.221); A6 r 70 centre (1358.018, -508.612) between (1423.227, -534.065) and (1374.243, -440.518); A7 r 100 centre (1516.382, -570.427) between (1423.227, -534.065) and (1519.438, -670.38); A8 r 150 centre (1524.023, -820.31) between (1601.431, -691.827) and (1519.438, -670.38); A9 r 500 centre (2457.606, -623.92) between (2199.578, -1052.198) and (2469.644, -1123.775); A10 r 110 centre (0, 0) between (16.283, 108.788) and (-25.496, -107.005); 1 further point
    constraints: 22 end point, 20 point on circle, 13 centre point
  sketch "Bucket_7"
    geometry: L1 (0, -20)-(-640.824, -20); L2 (99.176, 0)-(99.176, 10); L3 (-180.824, 0)-(-180.824, 25); L4 (0, 0)-(-180.824, 0); L5 (-180.824, 25)-(69.176, 25); L6 (99.176, 10)-(69.176, 25); L7 (-356.679, 581.068)-(-15.346, 25); L8 (-860.363, 891.232)-(-851.481, 826.214); L9 (-515.824, 1128)-(-836.02, 941.187); L10 (-1280.042, 545.155)-(-976.734, 19.869); L11 (-630.824, -10)-(0, -10); L12 (-630.824, 0)-(0, 0); L13 (-613.369, 1053.537)-(-943.37, 660.257); L14 (-606.842, 1045.759)-(-935.709, 653.829); L15 (0, -20)-(0, -10); L16 (0, -10)-(0, 0); L17 (-356.679, 581.068)-(-508.427, 1102.579); L18 (-511.303, 1112.465)-(-515.824, 1128); L19 (-419.219, 1199.918)-(-425.141, 1166.336); L20 (-409.371, 1198.182)-(-415.292, 1164.599); L21 (-429.989, 1159.412)-(-613.369, 1053.537); L22 (-419.219, 1199.918)-(-409.371, 1198.182); L23 (0, 0)-(99.176, 0); L24 (-606.842, 1045.759)-(-424.989, 1150.752); L25 (-691.058, -5.529)-(-949.951, -5.529); L26 (-1223.594, 696.836)-(-784.605, 849.466); L27 (-1185.527, 84.913)-(-968.841, -1.886); L28 (-1246.2, 229.24)-(-1184.02, 378.858); L29 (-1183.986, 378.801)-(-1121.865, 527.323); L30 (-784.605, 849.466)-(-1109.735, 544.789); C1 r 25 at (-810.824, 898); C2 r 45 at (-1189.112, 597.66); C3 r 40 at (-1144.623, 187.025); A1 r 50 centre (-810.824, 898) between (-836.02, 941.187) and (-860.363, 891.232); A2 r 110 centre (-1144.623, 187.025) between (-1246.2, 229.24) and (-1176.471, 81.737); A3 r 105 centre (-1189.112, 597.66) between (-1223.594, 696.836) and (-1280.042, 545.155); A4 r 408 centre (-630.824, 398) between (-943.37, 660.257) and (-630.824, -10); A5 r 418 centre (-630.824, 398) between (-739.856, -5.529) and (-630.824, -20); A6 r 398 centre (-630.824, 398) between (-935.709, 653.829) and (-630.824, 0); A7 r 10 centre (-434.989, 1168.072) between (-429.989, 1159.412) and (-425.141, 1166.336); A8 r 20 centre (-434.989, 1168.072) between (-424.989, 1150.752) and (-415.292, 1164.599); A9 r 50.8 centre (-949.951, 45.271) between (-968.841, -1.886) and (-949.951, -5.529); A10 r 50.8 centre (-1074.999, 507.721) between (-1109.735, 544.789) and (-1121.865, 527.323); A11 r 50.8 centre (-932.741, 45.271) between (-976.734, 19.869) and (-932.741, -5.529); 1 further point
    constraints: 60 end point, 24 point on circle, 14 centre point, 11 point on line
  sketch "FrontBucket_7"
    geometry: L1 (36.508, 713.207)-(-16.797, 670.2); L2 (-16.797, 670.2)-(-101.739, 335.484); L3 (-101.739, 335.484)-(-109.966, 2.719); L4 (8.288, -109.687)-(308.835, -86.978); L5 (308.835, -86.978)-(319.542, -83.051); L6 (19.324, 520.756)-(99.155, 741.781); L7 (99.155, 741.781)-(80.344, 748.575); L8 (80.344, 748.575)-(36.508, 713.207); L9 (1233.625, 258.517)-(1200.234, 261.682); L10 (1200.234, 261.682)-(1143.868, 239.874); L11 (1143.868, 239.874)-(1177.667, 236.867); L12 (1177.667, 236.867)-(1233.625, 258.517); L13 (967.076, 171.475)-(1143.868, 239.874); L14 (1181.276, 227.541)-(976.097, 148.159); L15 (976.097, 148.159)-(967.076, 171.475); L16 (1237.234, 249.191)-(1233.625, 258.517); L17 (1177.667, 236.867)-(1181.276, 227.541); L18 (1181.276, 227.541)-(1237.234, 249.191); L19 (332.219, -99.88)-(327.869, -88.635); L20 (332.219, -99.88)-(340.093, -96.834); L21 (327.869, -88.635)-(326.446, -84.958); L22 (630.662, 15.585)-(695.946, 40.843); L23 (340.093, -96.834)-(630.662, 15.585); L24 (971.406, 160.283)-(964.544, 144.762); L25 (971.406, 160.283)-(969.963, 164.014); L26 (695.946, 40.843)-(690.173, 55.765); L27 (969.963, 164.014)-(690.173, 55.765); L28 (695.946, 40.843)-(964.544, 144.762); L29 (271.723, 1081.905)-(246.908, 1104.472); L30 (246.908, 1104.472)-(15.69, 814.708); L31 (11.012, 759.335)-(43.462, 700.624); L32 (47.21, 660.849)-(-0.759, 514.651); L33 (556.412, -14.214)-(696.307, 39.911); L34 (696.307, 39.911)-(695.946, 40.843); L35 (594.585, 649.257)-(271.723, 1081.905); L36 (459.694, 596.673)-(459.353, 596.937); L37 (459.353, 596.937)-(498.23, 611.978); L38 (1112.062, 227.901)-(576.694, 642.28); L39 (995.062, 182.294)-(998.041, 183.455); L40 (499.228, 612.083)-(459.694, 596.673); L41 (459.694, 596.673)-(526.939, 544.624); L42 (606.946, 482.699)-(686.952, 420.773); L43 (766.958, 358.848)-(846.965, 296.922); L44 (926.971, 234.997)-(985.819, 189.448); L45 (995.055, 182.3)-(995.062, 182.294); L46 (998.041, 183.455)-(1130.882, 235.237); L47 (985.819, 189.448)-(995.055, 182.3); L48 (1130.882, 235.237)-(595.514, 649.616); C1 r 60 at (0, 0); C2 r 85 at (-189.66, 366.918); C3 r 25 at (54.772, 783.522); C4 r 62.5 at (-189.66, 366.918); A1 r 110 centre (0, 0) between (-109.966, 2.719) and (8.288, -109.687); A2 r 408 centre (403.06, 382.155) between (19.324, 520.756) and (16.94, 513.969); A3 r 50 centre (54.772, 783.522) between (15.69, 814.708) and (11.012, 759.335); A4 r 50 centre (-0.298, 676.437) between (47.21, 660.849) and (43.462, 700.624); A5 r 425 centre (403.06, 382.155) between (-0.759, 514.651) and (556.412, -14.214); 1 further point
    constraints: 96 end point, 10 point on circle, 9 centre point, 6 point on line
  sketch "A$C70327705_6"
    geometry: L1 (1293.342, 14.877)-(652.519, 14.877); L2 (1112.519, 47.877)-(1112.519, 51.877); L3 (652.519, 25)-(652.519, 14.997); L4 (652.519, 0)-(437.177, 0); L5 (437.177, 0)-(416.627, 29.348); L6 (662.519, 24.877)-(652.519, 24.877); L7 (1392.519, 34.877)-(1392.519, 44.877); L8 (1112.519, 34.877)-(1112.519, 59.877); L9 (1293.342, 34.877)-(1112.519, 34.877); L10 (1112.519, 59.877)-(1362.519, 59.877); L11 (1392.519, 44.877)-(1362.519, 59.877); L12 (936.663, 615.946)-(1277.997, 59.877); L13 (432.979, 926.11)-(441.861, 861.091); L14 (777.519, 1162.877)-(457.322, 976.064); L15 (116.871, 116.614)-(247.396, 77.132); L16 (100.413, 392.297)-(47.142, 264.117); L17 (374.881, 853.013)-(360.531, 832.814); L18 (440.113, 873.889)-(374.881, 853.013); L19 (9.07, 588.157)-(247.396, 77.132); L20 (662.519, 24.877)-(1293.342, 24.877); L21 (662.519, 34.877)-(1293.342, 34.877); L22 (679.974, 1088.415)-(349.973, 695.135); L23 (686.501, 1080.636)-(357.633, 688.707); L24 (1293.342, 14.877)-(1293.342, 24.877); L25 (1293.342, 24.877)-(1293.342, 34.877); L26 (936.663, 615.946)-(784.916, 1137.456); L27 (782.039, 1147.342)-(777.519, 1162.877); L28 (874.123, 1234.796)-(868.202, 1201.213); L29 (883.971, 1233.059)-(878.05, 1199.476); L30 (863.354, 1194.289)-(679.974, 1088.415); L31 (874.123, 1234.796)-(883.971, 1233.059); L32 (1293.342, 34.877)-(1392.519, 34.877); L33 (686.501, 1080.636)-(868.354, 1185.629); L34 (652.519, 0)-(652.519, 14.997); L35 (602.285, 29.348)-(293.569, 29.348); L36 (259.584, 50.998)-(247.396, 77.132); L37 (69.748, 731.714)-(508.737, 884.343); C1 r 25 at (482.519, 932.877); C2 r 45 at (104.231, 632.537); A1 r 50 centre (482.519, 932.877) between (457.322, 976.064) and (432.979, 926.11); A2 r 40 centre (148.72, 221.902) between (162.34, 259.512) and (186.286, 208.165); A3 r 110 centre (148.72, 221.902) between (47.142, 264.117) and (116.871, 116.614); A4 r 105 centre (104.231, 632.537) between (69.748, 731.714) and (9.07, 588.157); A5 r 408 centre (662.519, 432.877) between (349.973, 695.135) and (662.519, 24.877); A6 r 398 centre (662.519, 432.877) between (357.633, 688.707) and (662.519, 34.877); A7 r 37.5 centre (293.569, 66.848) between (259.584, 50.998) and (293.569, 29.348); A8 r 10 centre (858.354, 1202.949) between (863.354, 1194.289) and (868.202, 1201.213); A9 r 20 centre (858.354, 1202.949) between (868.354, 1185.629) and (878.05, 1199.476); 1 further point
    constraints: 74 end point, 20 point on circle, 16 point on line, 11 centre point
  sketch "A$C60B60B97_6"
    geometry: 1 further point
sketch "Sketch1"
  geometry: L1 (95.022, -681.286)-(272.857, -489.184) reference; L2 (278.529, -481.687)-(299.453, -447.453) reference; L3 (295.917, -416.857)-(172.052, -291.319) reference; L4 (108.329, 19.101)-(158.403, -264.884) reference; L5 (-225.117, -660.979)-(-108.413, 18.617) reference; L6 (-225.235, -722.613)-(-225.117, -660.979) reference; L7 (-198.661, -766.881)-(-24.713, -859.13) reference; L8 (3.19, -856.093)-(33.762, -830.109) reference; L9 (48.097, -808.832)-(84.242, -699.551) reference; C1 r 7.647 at (-15.419, -832.043) reference; C2 r 7.647 at (16.581, -745.788) reference; C3 r 7.647 at (193.039, -469.416) reference; C4 r 7.647 at (278.122, -434.416) reference; C5 r 4.688 at (-105, -250) reference; C6 r 4.688 at (-25, -250) reference; C7 r 4.688 at (-25, -100) reference; C8 r 4.688 at (-105, -100) reference; C9 r 17.5 at (-65, -190) reference; C10 r 40 at (0, -600) reference; C11 r 40 at (0, 0) reference; A1 r 47.5 centre (238, -456.916) between (272.857, -489.184) and (278.529, -481.687) reference; A2 r 25 centre (278.122, -434.416) between (299.453, -447.453) and (295.917, -416.857) reference; A3 r 50 centre (207.644, -256.202) between (158.403, -264.884) and (172.052, -291.319) reference; A4 r 110 centre (0, 0) between (108.329, 19.101) and (-108.413, 18.617) reference; A5 r 50 centre (-175.235, -722.709) between (-225.235, -722.613) and (-198.661, -766.881) reference; A6 r 25 centre (-13, -837.043) between (-24.713, -859.13) and (3.19, -856.093) reference; A7 r 47.5 centre (3, -793.916) between (33.762, -830.109) and (48.097, -808.832) reference; A8 r 50 centre (131.713, -715.252) between (95.022, -681.286) and (84.242, -699.551) reference
  node "Reference31"
node "Bucket_1:1"
node "Bucket_2:1"
node "Bucket_3:1"
node "Bucket_4:1"
node "Bucket_5:1"
node "Bucket_6:1"
node "Bucket_7:1"
